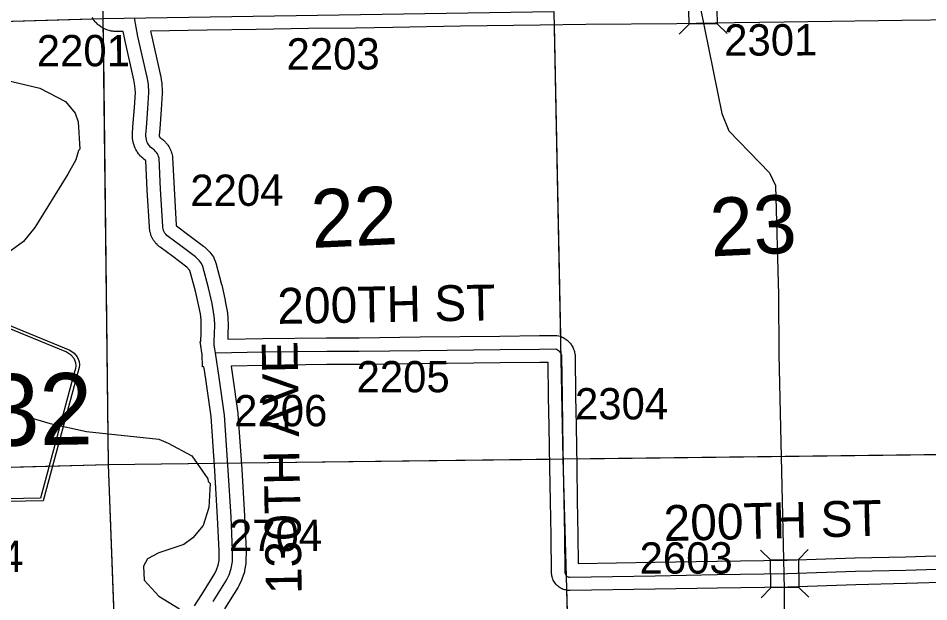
# Model space of a CAD drawing. Extents: x 128.7 to 185.5, y -21.4 to 12.6.
# Drawn here: x 136.899 to 138.935, y -5.909 to -4.606 of the extents above; entities that cross this region are included whole.
import ezdxf

# ---------------------------------------------------------------- set-up
doc = ezdxf.new("R2010")
doc.units = 0
for name, color, linetype in [('tdCoHydroRiver', 7, 'Continuous'), ('tdCoSecRdNmbr', 7, 'Continuous'), ('tdCoSecRdTxt', 7, 'Continuous'), ('tdCoSecRteBand', 7, 'Continuous'), ('tdCoSecRteCL', 7, 'Continuous'), ('tdCoSectLine', 7, 'Continuous'), ('tdCoSectLinePart', 7, 'Continuous'), ('tdCoSectNmbr', 7, 'Continuous'), ('tdCoShieldCoRteHrd', 7, 'Continuous'), ('tdCoStrucSec', 7, 'Continuous'), ('tdCoSurfGravel', 7, 'Continuous')]:
    doc.layers.add(name, color=color, linetype=linetype)

msp = doc.modelspace()

# ---------------------------------------------------------------- linework, layer by layer
at = {"layer": 'tdCoHydroRiver'}
for points in [[(138.4238, -4.5803), (138.4723, -4.8187), (138.4877, -4.8576), (138.579, -4.9511), (138.5925, -4.979), (138.5986, -5.2233), (138.5995, -5.3558), (138.6113, -5.8806), (138.6111, -6.0778)], [(136.8379, -4.7356), (136.9476, -4.7622), (137.0054, -4.792), (137.0267, -4.8181), (137.0336, -4.8368), (137.0371, -4.8983), (137.0341, -4.9015), (137.0284, -4.9222), (137.0105, -4.9543), (136.9369, -5.0734), (136.911, -5.1042), (136.8647, -5.1388)], [(136.8978, -5.4897), (136.971, -5.5111), (137.0521, -5.529), (137.2136, -5.5461), (137.2344, -5.5549), (137.2873, -5.5832), (137.3236, -5.6342), (137.3238, -5.6405), (137.3287, -5.6451), (137.3257, -5.6988), (137.3127, -5.7387), (137.2899, -5.7662), (137.2698, -5.781), (137.2136, -5.8001), (137.1888, -5.8135), (137.1798, -5.8296), (137.1808, -5.8611), (137.2135, -5.8964), (137.2601, -5.9249)]]:
    msp.add_lwpolyline(points, dxfattribs=at)
at = {"layer": 'tdCoSecRteBand'}
for points in [[(137.2937, -5.9181), (137.3097, -5.8927), (137.3391, -5.8461), (137.343, -5.838), (137.3466, -5.8275), (137.3483, -5.8166), (137.3487, -5.7947), (137.3451, -5.7207), (137.3392, -5.6169), (137.3309, -5.4952), (137.3187, -5.4122), (137.3187, -5.4122), (137.3187, -5.4122), (137.3151, -5.3875), (137.3146, -5.384), (137.3111, -5.3841), (137.3105, -5.356), (137.3094, -5.3483), (137.3082, -5.3409), (137.3079, -5.3389), (137.3079, -5.3377), (137.3065, -5.3281), (137.3076, -5.3279), (137.3076, -5.3278), (137.3076, -5.3267), (137.3076, -5.3256), (137.3083, -5.3098), (137.3086, -5.2913), (137.3081, -5.2794), (137.3066, -5.266), (137.3035, -5.2489), (137.2959, -5.2154), (137.2833, -5.1693), (137.283, -5.1684), (137.2827, -5.1681), (137.2761, -5.1617), (137.2449, -5.1382), (137.2164, -5.1171), (137.2155, -5.1164), (137.2147, -5.1157), (137.2122, -5.1136), (137.2109, -5.1124), (137.2097, -5.1112), (137.2074, -5.1087), (137.2063, -5.1075), (137.2053, -5.1061), (137.2033, -5.1034), (137.2023, -5.102), (137.2014, -5.1005), (137.1997, -5.0976), (137.1989, -5.0961), (137.1982, -5.0946), (137.1969, -5.0915), (137.1962, -5.0899), (137.1957, -5.0883), (137.1948, -5.0851), (137.1943, -5.0834), (137.194, -5.0818), (137.1934, -5.0785), (137.1931, -5.0768), (137.1929, -5.0751), (137.1927, -5.0717), (137.1927, -5.0717), (137.1927, -5.0716), (137.1878, -4.9897), (137.1878, -4.9895), (137.1878, -4.9894), (137.1845, -4.9234), (137.1835, -4.9227), (137.1806, -4.9206), (137.1793, -4.9196), (137.1782, -4.9186), (137.1753, -4.9159), (137.1741, -4.9149), (137.173, -4.9137), (137.1704, -4.9108), (137.1694, -4.9096), (137.1684, -4.9083), (137.1662, -4.9051), (137.1652, -4.9038), (137.1644, -4.9024), (137.1625, -4.899), (137.1617, -4.8976), (137.1611, -4.8961), (137.1596, -4.8926), (137.1589, -4.8911), (137.1584, -4.8895), (137.1573, -4.8858), (137.1568, -4.8843), (137.1565, -4.8827), (137.1558, -4.8789), (137.1554, -4.8773), (137.1553, -4.8757), (137.155, -4.8719), (137.1548, -4.8703), (137.1549, -4.8687), (137.1549, -4.8648), (137.1549, -4.864), (137.155, -4.8633), (137.156, -4.8488), (137.156, -4.8487), (137.156, -4.8486), (137.1592, -4.8052), (137.1615, -4.7718), (137.1605, -4.7565), (137.1582, -4.7435), (137.1379, -4.6532), (137.1378, -4.6528), (137.1377, -4.6523), (137.1344, -4.6351), (137.1293, -4.6351), (137.1155, -4.6353), (137.1131, -4.6353), (137.1106, -4.6349), (137.1068, -4.6343), (137.105, -4.634), (137.1032, -4.6335), (137.0995, -4.6324), (137.0977, -4.6319), (137.0959, -4.6311), (137.0924, -4.6296), (137.0907, -4.6289), (137.0891, -4.6279), (137.0858, -4.6259), (137.0842, -4.625), (137.0827, -4.6238), (137.0796, -4.6215), (137.0782, -4.6203), (137.0768, -4.619), (137.0741, -4.6163), (137.0728, -4.615), (137.0716, -4.6135), (137.0693, -4.6105), (137.0681, -4.609), (137.0672, -4.6073), (137.0652, -4.6041)], [(139.002, -4.6091), (138.8745, -4.6108), (138.6121, -4.6145), (138.6121, -4.6145), (138.6121, -4.6145), (138.5004, -4.616), (138.3715, -4.618), (138.3714, -4.618), (138.3713, -4.618), (138.1684, -4.6197), (138.0664, -4.6212), (138.0664, -4.6212), (138.0664, -4.6212), (137.8884, -4.6237), (137.7366, -4.6266), (137.7365, -4.6266), (137.7365, -4.6266), (137.6536, -4.6279), (137.6535, -4.6279), (137.6534, -4.6279), (137.5485, -4.6286), (137.4313, -4.6311), (137.4312, -4.6311), (137.4311, -4.6311), (137.3221, -4.6323), (137.1954, -4.6345), (137.1965, -4.6404), (137.2169, -4.731), (137.2171, -4.7317), (137.2172, -4.7324), (137.2199, -4.7476), (137.2202, -4.7493), (137.2203, -4.7509), (137.2215, -4.7699), (137.2217, -4.7719), (137.2215, -4.774), (137.2191, -4.8095), (137.219, -4.8095), (137.219, -4.8096), (137.2158, -4.8529), (137.2149, -4.8666), (137.2149, -4.8682), (137.2149, -4.8689), (137.2151, -4.8696), (137.2153, -4.8703), (137.2156, -4.8709), (137.2159, -4.8715), (137.2163, -4.8721), (137.2168, -4.8726), (137.2173, -4.873), (137.2191, -4.8744), (137.2194, -4.8746), (137.2197, -4.8748), (137.2224, -4.8769), (137.2237, -4.8779), (137.2249, -4.8791), (137.2274, -4.8814), (137.2286, -4.8826), (137.2297, -4.8839), (137.2319, -4.8865), (137.233, -4.8878), (137.2339, -4.8892), (137.2358, -4.8921), (137.2367, -4.8935), (137.2374, -4.895), (137.239, -4.898), (137.2398, -4.8995), (137.2403, -4.9011), (137.2415, -4.9043), (137.2421, -4.9059), (137.2425, -4.9075), (137.2434, -4.9108), (137.2441, -4.9137), (137.2442, -4.9166), (137.2477, -4.9863), (137.2526, -5.0679), (137.2527, -5.0693), (137.253, -5.0695), (137.2807, -5.0901), (137.2808, -5.0901), (137.2809, -5.0902), (137.3137, -5.1148), (137.3152, -5.116), (137.3166, -5.1173), (137.3257, -5.1262), (137.3269, -5.1273), (137.3279, -5.1286), (137.3326, -5.1343), (137.3359, -5.1383), (137.3377, -5.1433), (137.3402, -5.1502), (137.3406, -5.1513), (137.3409, -5.1524), (137.3539, -5.2002), (137.3541, -5.2008), (137.3543, -5.2015), (137.3622, -5.2363), (137.3623, -5.2369), (137.3624, -5.2375), (137.3659, -5.2562), (137.366, -5.2573), (137.3662, -5.2583), (137.3679, -5.2739), (137.368, -5.275), (137.3681, -5.2761), (137.3685, -5.2899), (137.3686, -5.2906), (137.3686, -5.2914), (137.3683, -5.3111), (137.3683, -5.3116), (137.3683, -5.3121), (137.3678, -5.3228), (137.4463, -5.3211), (137.4465, -5.3211), (137.4466, -5.3211), (137.5889, -5.3193), (137.5891, -5.3193), (137.5893, -5.3193), (137.6616, -5.3193), (137.798, -5.3176), (137.798, -5.3176), (137.7981, -5.3176), (137.9761, -5.3157), (138.0646, -5.3147), (138.0991, -5.3142), (138.1036, -5.3141), (138.108, -5.3154), (138.1108, -5.3162), (138.1131, -5.3169), (138.1152, -5.3179), (138.1179, -5.3192), (138.12, -5.3202), (138.122, -5.3216), (138.1244, -5.3232), (138.1263, -5.3246), (138.1281, -5.3262), (138.1302, -5.3282), (138.1319, -5.3299), (138.1333, -5.3318), (138.1351, -5.3341), (138.1365, -5.336), (138.1377, -5.3381), (138.139, -5.3407), (138.1402, -5.3428), (138.141, -5.345), (138.1419, -5.3478), (138.1427, -5.35), (138.1431, -5.3524), (138.1436, -5.3552), (138.144, -5.3577), (138.1441, -5.3601), (138.145, -5.45), (138.1463, -5.5165), (138.1463, -5.5165), (138.1463, -5.5166), (138.1478, -5.6073), (138.149, -5.6832), (138.1505, -5.7606), (138.1505, -5.7607), (138.1505, -5.7608), (138.1512, -5.8236)], [(139.0864, -5.8622), (138.8846, -5.8684), (138.8845, -5.8684), (138.8844, -5.8684), (138.7716, -5.8711), (138.6201, -5.8762), (138.6198, -5.8763), (138.6195, -5.8763), (138.4623, -5.8785), (138.3235, -5.8809), (138.3234, -5.8809), (138.3234, -5.8809), (138.133, -5.8839), (138.1317, -5.8839), (138.1304, -5.8838), (138.1283, -5.8837), (138.1255, -5.8835), (138.1227, -5.8827), (138.1207, -5.8822), (138.1179, -5.8814), (138.1154, -5.8802), (138.1135, -5.8793), (138.1109, -5.878), (138.1086, -5.8763), (138.107, -5.8751), (138.1047, -5.8733), (138.1028, -5.8712), (138.1014, -5.8697), (138.0995, -5.8676), (138.098, -5.8651), (138.0969, -5.8634), (138.0954, -5.8609), (138.0944, -5.8582), (138.0937, -5.8563), (138.0927, -5.8536), (138.0922, -5.8508), (138.0919, -5.8487), (138.0915, -5.8465), (138.0915, -5.8442), (138.0905, -5.7616), (138.089, -5.6843), (138.089, -5.6843), (138.089, -5.6842), (138.0878, -5.6083), (138.0863, -5.5176), (138.0851, -5.451), (138.0851, -5.4509), (138.0851, -5.4508), (138.0842, -5.3744), (138.0654, -5.3747), (138.0654, -5.3747), (138.0653, -5.3747), (137.9768, -5.3756), (137.7988, -5.3776), (137.6622, -5.3793), (137.662, -5.3793), (137.6618, -5.3793), (137.5895, -5.3793), (137.4475, -5.3811), (137.3751, -5.3827), (137.3781, -5.4035), (137.3904, -5.4876), (137.3906, -5.4888), (137.3907, -5.4899), (137.3991, -5.613), (137.3991, -5.6132), (137.3991, -5.6133), (137.405, -5.7174), (137.405, -5.7175), (137.405, -5.7176), (137.4087, -5.7928), (137.4088, -5.7939), (137.4088, -5.7949), (137.4083, -5.8198), (137.4082, -5.8219), (137.4079, -5.8239), (137.4054, -5.8395), (137.405, -5.842), (137.4042, -5.8444), (137.3993, -5.8589), (137.3987, -5.8606), (137.3979, -5.8622), (137.3925, -5.8736), (137.3918, -5.8752), (137.3908, -5.8767), (137.3605, -5.9247)], [(138.1512, -5.8236), (138.3224, -5.8209), (138.4612, -5.8185), (138.4613, -5.8185), (138.4614, -5.8185), (138.6184, -5.8163), (138.7698, -5.8111), (138.7699, -5.8111), (138.7701, -5.8111), (138.8829, -5.8084), (139.0852, -5.8023)]]:
    msp.add_lwpolyline(points, dxfattribs=at)
at = {"layer": 'tdCoSecRteCL'}
for points in [[(137.3405, -5.3534), (137.3391, -5.3438), (137.3378, -5.3361), (137.3376, -5.327), (137.3383, -5.3107), (137.3386, -5.291), (137.3381, -5.2772), (137.3363, -5.2616), (137.3329, -5.2429), (137.325, -5.2081), (137.3119, -5.1603), (137.3095, -5.1534), (137.3048, -5.1477), (137.2957, -5.1388), (137.2629, -5.1142), (137.2343, -5.093), (137.2317, -5.0908), (137.2294, -5.0883), (137.2274, -5.0856), (137.2258, -5.0827), (137.2244, -5.0796), (137.2235, -5.0764), (137.2229, -5.0731), (137.2227, -5.0698), (137.2177, -4.9879), (137.2143, -4.9181), (137.2134, -4.9148), (137.2122, -4.9116), (137.2107, -4.9086), (137.2088, -4.9057), (137.2066, -4.9031), (137.2042, -4.9007), (137.2015, -4.8986), (137.1983, -4.8963), (137.1954, -4.8937), (137.1928, -4.8908), (137.1906, -4.8876), (137.1886, -4.8842), (137.1871, -4.8807), (137.1859, -4.8769), (137.1852, -4.8731), (137.1849, -4.8692), (137.1849, -4.8653), (137.1859, -4.8508), (137.1891, -4.8074), (137.1916, -4.7719), (137.1904, -4.7529), (137.1876, -4.7376), (137.1672, -4.6466), (137.1591, -4.6049)], [(137.3405, -5.3534), (137.447, -5.3511), (137.5893, -5.3493), (137.6618, -5.3493), (137.7984, -5.3476), (137.9765, -5.3456), (138.065, -5.3447), (138.0995, -5.3442), (138.1023, -5.345), (138.1049, -5.3462), (138.1073, -5.3479), (138.1095, -5.3499), (138.1112, -5.3522), (138.1126, -5.3548), (138.1136, -5.3576), (138.1141, -5.3604), (138.115, -5.4505), (138.1163, -5.517), (138.1178, -5.6078), (138.119, -5.6837), (138.1205, -5.7612), (138.1215, -5.8438), (138.1218, -5.8458), (138.1225, -5.8478), (138.1236, -5.8495), (138.125, -5.8511), (138.1266, -5.8523), (138.1285, -5.8532), (138.1305, -5.8538), (138.1326, -5.8539), (138.3229, -5.8509), (138.4618, -5.8485), (138.6191, -5.8463), (138.7708, -5.8411), (138.8837, -5.8384), (139.1159, -5.8313)], [(137.3351, -5.9087), (137.3654, -5.8606), (137.3709, -5.8493), (137.3758, -5.8348), (137.3783, -5.8192), (137.3788, -5.7943), (137.3751, -5.7191), (137.3691, -5.615), (137.3608, -5.492), (137.3484, -5.4079), (137.3405, -5.3534)]]:
    msp.add_lwpolyline(points, dxfattribs=at)
at = {"layer": 'tdCoSectLine'}
for points in [[(137.0693, -3.6163), (137.0889, -4.6062)], [(137.0889, -4.6062), (138.0965, -4.5907)], [(138.0965, -4.5907), (138.117, -5.59)], [(136.0691, -4.6358), (137.0889, -4.6062)], [(137.0889, -4.6062), (137.1003, -5.6022)], [(137.1003, -5.6022), (138.117, -5.59)], [(138.117, -5.59), (139.1109, -5.5779)], [(138.117, -5.59), (138.1452, -6.59)], [(136.0983, -5.6299), (137.1003, -5.6022)], [(137.1003, -5.6022), (137.1386, -6.6181)]]:
    msp.add_lwpolyline(points, dxfattribs=at)
at = {"layer": 'tdCoSectLinePart'}
for points in [[(136.0692, -4.6358), (137.0667, -4.6068)], [(137.0891, -4.6279), (137.1003, -5.6022)], [(138.0971, -4.6209), (138.1114, -5.3167)], [(137.3971, -5.5986), (138.0872, -5.5903)], [(138.1472, -5.5896), (139.0808, -5.5783)], [(136.5393, -5.6177), (137.1003, -5.6022)], [(137.1003, -5.6022), (137.3376, -5.5993)], [(137.1003, -5.6022), (137.1181, -6.075)], [(138.1253, -5.8829), (138.1452, -6.59)]]:
    msp.add_lwpolyline(points, dxfattribs=at)
at = {"layer": 'tdCoShieldCoRteHrd'}
for points in [[(136.716, -5.6882), (136.6286, -5.4069), (136.6245, -5.3939), (136.6236, -5.388), (136.6235, -5.3802), (136.6275, -5.3698), (136.6346, -5.3611), (136.6441, -5.3543), (136.8099, -5.2787), (136.8174, -5.277), (136.8278, -5.2758), (136.8383, -5.2766), (136.8458, -5.2781), (137.0145, -5.3472), (137.0242, -5.3537), (137.0316, -5.362), (137.036, -5.3722), (137.0362, -5.3801), (137.0356, -5.3859), (137.0319, -5.3992), (136.9555, -5.6836)], [(136.7217, -5.6818), (136.6367, -5.4081), (136.6327, -5.3955), (136.6319, -5.3899), (136.6318, -5.3824), (136.6357, -5.3724), (136.6425, -5.3641), (136.6516, -5.3575), (136.8108, -5.285), (136.818, -5.2833), (136.828, -5.2822), (136.838, -5.2829), (136.8452, -5.2843), (137.0071, -5.3507), (137.0164, -5.3569), (137.0236, -5.3649), (137.0278, -5.3748), (137.028, -5.3823), (137.0274, -5.3879), (137.0239, -5.4006), (136.9495, -5.6774)]]:
    msp.add_lwpolyline(points, close=True, dxfattribs=at)
at = {"layer": 'tdCoStrucSec'}
for p, q in [((138.3988, -4.6189), (138.377, -4.6413)), ((138.4614, -4.6179), (138.4838, -4.6397)), ((138.5807, -5.8155), (138.5583, -5.7937)), ((138.6433, -5.8146), (138.6652, -5.7922)), ((138.5816, -5.8781), (138.5598, -5.9005)), ((138.6442, -5.8772), (138.6667, -5.899))]:
    msp.add_line(p, q, dxfattribs=at)
for points in [[(138.3978, -4.5563), (138.4604, -4.5553), (138.4614, -4.6179), (138.3988, -4.6189)], [(138.5807, -5.8155), (138.6433, -5.8146), (138.6442, -5.8772), (138.5816, -5.8781)]]:
    msp.add_lwpolyline(points, close=True, dxfattribs=at)
at = {"layer": 'tdCoSurfGravel'}
for points in [[(137.3351, -5.9087), (137.3654, -5.8606), (137.3709, -5.8493), (137.3758, -5.8348), (137.3783, -5.8192), (137.3788, -5.7943), (137.3751, -5.7191), (137.3691, -5.615), (137.3608, -5.492), (137.3484, -5.4079), (137.3405, -5.3534), (137.3391, -5.3438), (137.3378, -5.3361), (137.3376, -5.327), (137.3383, -5.3107), (137.3386, -5.291), (137.3381, -5.2772), (137.3363, -5.2616), (137.3329, -5.2429), (137.325, -5.2081), (137.3119, -5.1603), (137.3095, -5.1534), (137.3048, -5.1477), (137.2957, -5.1388), (137.2629, -5.1142), (137.2343, -5.093), (137.2317, -5.0908), (137.2294, -5.0883), (137.2274, -5.0856), (137.2258, -5.0827), (137.2244, -5.0796), (137.2235, -5.0764), (137.2229, -5.0731), (137.2227, -5.0698), (137.2177, -4.9879), (137.2143, -4.9181), (137.2134, -4.9148), (137.2122, -4.9116), (137.2107, -4.9086), (137.2088, -4.9057), (137.2066, -4.9031), (137.2042, -4.9007), (137.2015, -4.8986), (137.1983, -4.8963), (137.1954, -4.8937), (137.1928, -4.8908), (137.1906, -4.8876), (137.1886, -4.8842), (137.1871, -4.8807), (137.1859, -4.8769), (137.1852, -4.8731), (137.1849, -4.8692), (137.1849, -4.8653), (137.1859, -4.8508), (137.1891, -4.8074), (137.1916, -4.7719), (137.1904, -4.7529), (137.1876, -4.7376), (137.1672, -4.6466), (137.1591, -4.6049)], [(137.3405, -5.3534), (137.447, -5.3511), (137.5893, -5.3493), (137.6618, -5.3493), (137.7984, -5.3476), (137.9765, -5.3456), (138.065, -5.3447), (138.0995, -5.3442), (138.1023, -5.345), (138.1049, -5.3462), (138.1073, -5.3479), (138.1095, -5.3499), (138.1112, -5.3522), (138.1126, -5.3548), (138.1136, -5.3576), (138.1141, -5.3604), (138.115, -5.4505), (138.1163, -5.517), (138.1178, -5.6078), (138.119, -5.6837), (138.1205, -5.7612), (138.1215, -5.8438), (138.1218, -5.8458), (138.1225, -5.8478), (138.1236, -5.8495), (138.125, -5.8511), (138.1266, -5.8523), (138.1285, -5.8532), (138.1305, -5.8538), (138.1326, -5.8539), (138.3229, -5.8509), (138.4618, -5.8485), (138.6191, -5.8463), (138.7708, -5.8411), (138.8837, -5.8384), (139.1159, -5.8313)]]:
    msp.add_lwpolyline(points, dxfattribs=at)

# ---------------------------------------------------------------- texts
at = {"layer": 'tdCoSecRdNmbr'}
for s, rotation, p in [('2301', 0.1055, (138.4775, -4.6893)), ('2201', 0.1043, (136.941, -4.7133)), ('2203', 0.1048, (137.4993, -4.7205)), ('2204', 0.1046, (137.2842, -5.0251)), ('2205', 0.1048, (137.6558, -5.4415)), ('2304', 0.1052, (138.144, -5.502)), ('2206', 0.1046, (137.3822, -5.5174)), ('2704', 0.1046, (137.3706, -5.7958)), ('2804', 0.1041, (136.7029, -5.843)), ('2603', 0.1053, (138.2884, -5.8464))]:
    msp.add_text(s, height=0.07, rotation=rotation, dxfattribs=at).set_placement(p)
at = {"layer": 'tdCoSecRdTxt'}
for s, rotation, p in [('200TH ST', 0.9561, (137.4794, -5.2885)), ('130TH AVE', 91, (137.5334, -5.8913)), ('200TH ST', 1.4174, (138.3431, -5.7737))]:
    msp.add_text(s, height=0.08, rotation=rotation, dxfattribs=at).set_placement(p)
at = {"layer": 'tdCoSectNmbr'}
for s, rotation, p in [('22', 2.6571, (137.5566, -5.119)), ('23', 2.6578, (138.4484, -5.1379))]:
    msp.add_text(s, height=0.13, rotation=rotation, dxfattribs=at).set_placement(p)
at = {"layer": 'tdCoShieldCoRteHrd'}
msp.add_text('Y32', height=0.16, rotation=1.1022, dxfattribs=at).set_placement((136.6864, -5.5645))

doc.saveas('drawing.dxf')
